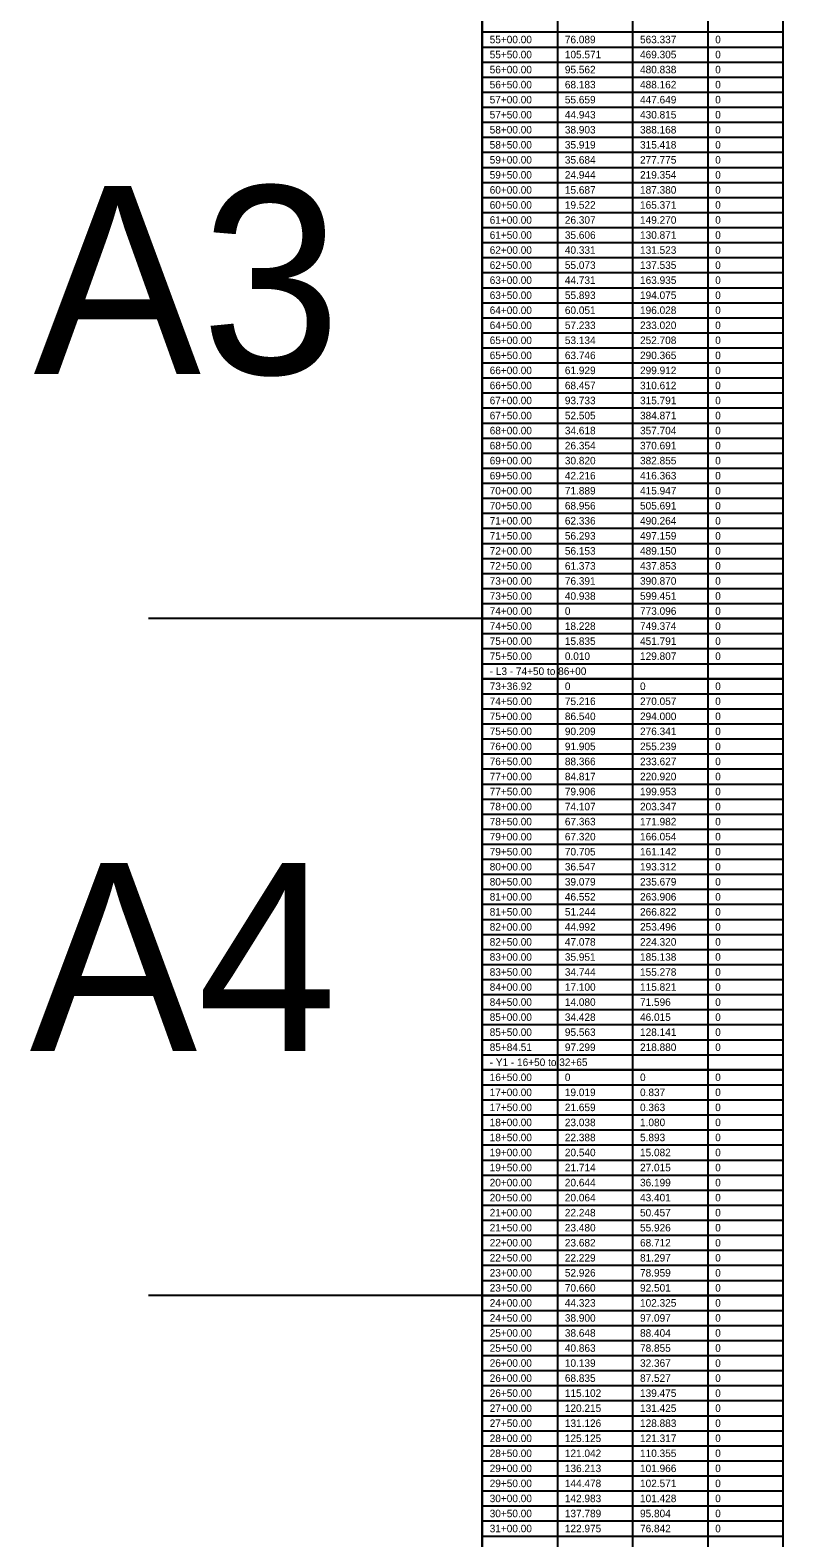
# Model space of a CAD drawing. Extents: x -124 to 80, y -10800 to 19.
# Drawn here: x -120.3 to 80, y -784.5 to -383.5 of the extents above; entities that cross this region are included whole.
import ezdxf

# ---------------------------------------------------------------- set-up
doc = ezdxf.new("R2010")
doc.units = 0
for name, color, linetype in [('Prop Shade Light', 7, 'Continuous'), ('Prop XSC Text', 7, 'Continuous'), ('Scratch_Level_1', 7, 'Continuous'), ('Scratch_Level_3', 7, 'Continuous'), ('Sheet Clip Boundary CELL', 7, 'Continuous')]:
    doc.layers.add(name, color=color, linetype=linetype)

msp = doc.modelspace()

# ---------------------------------------------------------------- linework, layer by layer
at = {"layer": 'Prop Shade Light'}
for points in [[(0, -552), (80, -552), (80, -556), (0, -556)], [(0, -656), (80, -656), (80, -660), (0, -660)]]:
    msp.add_lwpolyline(points, close=True, dxfattribs=at)
at = {"layer": 'Scratch_Level_1'}
for p, q in [((0, 0), (0, -6480)), ((20, 0), (20, -6480)), ((40, 0), (40, -6480)), ((60, 0), (60, -6480)), ((80, 0), (80, -6480)), ((0, -384), (80, -384)), ((0, -388), (80, -388)), ((0, -392), (80, -392)), ((0, -396), (80, -396)), ((0, -400), (80, -400)), ((0, -404), (80, -404)), ((0, -408), (80, -408)), ((0, -412), (80, -412)), ((0, -416), (80, -416)), ((0, -420), (80, -420)), ((0, -424), (80, -424)), ((0, -428), (80, -428)), ((0, -432), (80, -432)), ((0, -436), (80, -436)), ((0, -440), (80, -440)), ((0, -444), (80, -444)), ((0, -448), (80, -448)), ((0, -452), (80, -452)), ((0, -456), (80, -456)), ((0, -460), (80, -460)), ((0, -464), (80, -464)), ((0, -468), (80, -468)), ((0, -472), (80, -472)), ((0, -476), (80, -476)), ((0, -480), (80, -480)), ((0, -484), (80, -484)), ((0, -488), (80, -488)), ((0, -492), (80, -492)), ((0, -496), (80, -496)), ((0, -500), (80, -500)), ((0, -504), (80, -504)), ((0, -508), (80, -508)), ((0, -512), (80, -512)), ((0, -516), (80, -516)), ((0, -520), (80, -520)), ((0, -524), (80, -524)), ((0, -528), (80, -528)), ((0, -532), (80, -532)), ((0, -536), (80, -536)), ((0, -540), (-88.81, -540)), ((0, -540), (80, -540)), ((0, -544), (80, -544)), ((0, -548), (80, -548)), ((0, -552), (80, -552)), ((0, -556), (80, -556)), ((0, -560), (80, -560)), ((0, -564), (80, -564)), ((0, -568), (80, -568)), ((0, -572), (80, -572)), ((0, -576), (80, -576)), ((0, -580), (80, -580)), ((0, -584), (80, -584)), ((0, -588), (80, -588)), ((0, -592), (80, -592)), ((0, -596), (80, -596)), ((0, -600), (80, -600)), ((0, -604), (80, -604)), ((0, -608), (80, -608)), ((0, -612), (80, -612)), ((0, -616), (80, -616)), ((0, -620), (80, -620)), ((0, -624), (80, -624)), ((0, -628), (80, -628)), ((0, -632), (80, -632)), ((0, -636), (80, -636)), ((0, -640), (80, -640)), ((0, -644), (80, -644)), ((0, -648), (80, -648)), ((0, -652), (80, -652)), ((0, -656), (80, -656)), ((0, -660), (80, -660)), ((0, -664), (80, -664)), ((0, -668), (80, -668)), ((0, -672), (80, -672)), ((0, -676), (80, -676)), ((0, -680), (80, -680)), ((0, -684), (80, -684)), ((0, -688), (80, -688)), ((0, -692), (80, -692)), ((0, -696), (80, -696)), ((0, -700), (80, -700)), ((0, -704), (80, -704)), ((0, -708), (80, -708)), ((0, -712), (80, -712)), ((0, -716), (80, -716)), ((0, -720), (-88.81, -720)), ((0, -720), (80, -720)), ((0, -724), (80, -724)), ((0, -728), (80, -728)), ((0, -732), (80, -732)), ((0, -736), (80, -736)), ((0, -740), (80, -740)), ((0, -744), (80, -744)), ((0, -748), (80, -748)), ((0, -752), (80, -752)), ((0, -756), (80, -756)), ((0, -760), (80, -760)), ((0, -764), (80, -764)), ((0, -768), (80, -768)), ((0, -772), (80, -772)), ((0, -776), (80, -776)), ((0, -780), (80, -780)), ((0, -784), (80, -784))]:
    msp.add_line(p, q, dxfattribs=at)
at = {"layer": 'Sheet Clip Boundary CELL'}
for points in [[(0, -360), (80, -360), (80, -540), (0, -540)], [(0, -540), (80, -540), (80, -720), (0, -720)], [(0, -720), (80, -720), (80, -900), (0, -900)]]:
    msp.add_lwpolyline(points, close=True, dxfattribs=at)

# ---------------------------------------------------------------- texts
at = {"layer": 'Prop XSC Text'}
for s, p in [('55+00.00', (2, -387)), ('76.089', (22, -387)), ('563.337', (42, -387)), ('0', (62, -387)), ('55+50.00', (2, -391)), ('105.571', (22, -391)), ('469.305', (42, -391)), ('0', (62, -391)), ('56+00.00', (2, -395)), ('95.562', (22, -395)), ('480.838', (42, -395)), ('0', (62, -395)), ('56+50.00', (2, -399)), ('57+00.00', (2, -403)), ('55.659', (22, -403)), ('68.183', (22, -399)), ('488.162', (42, -399)), ('447.649', (42, -403)), ('0', (62, -399)), ('0', (62, -403)), ('57+50.00', (2, -407)), ('44.943', (22, -407)), ('430.815', (42, -407)), ('0', (62, -407)), ('58+00.00', (2, -411)), ('38.903', (22, -411)), ('388.168', (42, -411)), ('0', (62, -411)), ('58+50.00', (2, -415)), ('35.919', (22, -415)), ('315.418', (42, -415)), ('0', (62, -415)), ('59+00.00', (2, -419)), ('35.684', (22, -419)), ('277.775', (42, -419)), ('0', (62, -419)), ('59+50.00', (2, -423)), ('24.944', (22, -423)), ('219.354', (42, -423)), ('0', (62, -423)), ('60+00.00', (2, -427)), ('15.687', (22, -427)), ('187.380', (42, -427)), ('0', (62, -427)), ('60+50.00', (2, -431)), ('19.522', (22, -431)), ('165.371', (42, -431)), ('0', (62, -431)), ('61+00.00', (2, -435)), ('26.307', (22, -435)), ('149.270', (42, -435)), ('0', (62, -435)), ('61+50.00', (2, -439)), ('35.606', (22, -439)), ('130.871', (42, -439)), ('0', (62, -439)), ('62+00.00', (2, -443)), ('40.331', (22, -443)), ('131.523', (42, -443)), ('0', (62, -443)), ('62+50.00', (2, -447)), ('55.073', (22, -447)), ('137.535', (42, -447)), ('0', (62, -447)), ('63+00.00', (2, -451)), ('44.731', (22, -451)), ('163.935', (42, -451)), ('0', (62, -451)), ('63+50.00', (2, -455)), ('55.893', (22, -455)), ('194.075', (42, -455)), ('0', (62, -455)), ('64+00.00', (2, -459)), ('60.051', (22, -459)), ('196.028', (42, -459)), ('0', (62, -459)), ('64+50.00', (2, -463)), ('57.233', (22, -463)), ('233.020', (42, -463)), ('0', (62, -463)), ('65+00.00', (2, -467)), ('53.134', (22, -467)), ('252.708', (42, -467)), ('0', (62, -467)), ('65+50.00', (2, -471)), ('63.746', (22, -471)), ('290.365', (42, -471)), ('0', (62, -471)), ('66+00.00', (2, -475)), ('61.929', (22, -475)), ('299.912', (42, -475)), ('0', (62, -475)), ('66+50.00', (2, -479)), ('68.457', (22, -479)), ('310.612', (42, -479)), ('0', (62, -479)), ('67+00.00', (2, -483)), ('93.733', (22, -483)), ('315.791', (42, -483)), ('0', (62, -483)), ('67+50.00', (2, -487)), ('52.505', (22, -487)), ('384.871', (42, -487)), ('0', (62, -487)), ('68+00.00', (2, -491)), ('34.618', (22, -491)), ('357.704', (42, -491)), ('0', (62, -491)), ('68+50.00', (2, -495)), ('26.354', (22, -495)), ('370.691', (42, -495)), ('0', (62, -495)), ('69+00.00', (2, -499)), ('30.820', (22, -499)), ('382.855', (42, -499)), ('0', (62, -499)), ('69+50.00', (2, -503)), ('42.216', (22, -503)), ('416.363', (42, -503)), ('0', (62, -503)), ('70+00.00', (2, -507)), ('71.889', (22, -507)), ('415.947', (42, -507)), ('0', (62, -507)), ('70+50.00', (2, -511)), ('68.956', (22, -511)), ('505.691', (42, -511)), ('0', (62, -511)), ('71+00.00', (2, -515)), ('62.336', (22, -515)), ('490.264', (42, -515)), ('0', (62, -515)), ('71+50.00', (2, -519)), ('56.293', (22, -519)), ('497.159', (42, -519)), ('0', (62, -519)), ('72+00.00', (2, -523)), ('56.153', (22, -523)), ('489.150', (42, -523)), ('0', (62, -523)), ('72+50.00', (2, -527)), ('61.373', (22, -527)), ('437.853', (42, -527)), ('0', (62, -527)), ('73+00.00', (2, -531)), ('76.391', (22, -531)), ('390.870', (42, -531)), ('0', (62, -531)), ('73+50.00', (2, -535)), ('40.938', (22, -535)), ('599.451', (42, -535)), ('0', (62, -535)), ('74+00.00', (2, -539)), ('0', (22, -539)), ('773.096', (42, -539)), ('0', (62, -539)), ('74+50.00', (2, -543)), ('18.228', (22, -543)), ('749.374', (42, -543)), ('0', (62, -543)), ('75+00.00', (2, -547)), ('15.835', (22, -547)), ('451.791', (42, -547)), ('0', (62, -547)), ('75+50.00', (2, -551)), ('0.010', (22, -551)), ('129.807', (42, -551)), ('0', (62, -551)), ('- L3 - 74+50 to 86+00', (2, -555)), ('73+36.92', (2, -559)), ('0', (22, -559)), ('0', (42, -559)), ('0', (62, -559)), ('74+50.00', (2, -563)), ('75.216', (22, -563)), ('270.057', (42, -563)), ('0', (62, -563)), ('75+00.00', (2, -567)), ('86.540', (22, -567)), ('294.000', (42, -567)), ('0', (62, -567)), ('75+50.00', (2, -571)), ('90.209', (22, -571)), ('276.341', (42, -571)), ('0', (62, -571)), ('76+00.00', (2, -575)), ('91.905', (22, -575)), ('255.239', (42, -575)), ('0', (62, -575)), ('76+50.00', (2, -579)), ('88.366', (22, -579)), ('233.627', (42, -579)), ('0', (62, -579)), ('77+00.00', (2, -583)), ('84.817', (22, -583)), ('220.920', (42, -583)), ('0', (62, -583)), ('77+50.00', (2, -587)), ('79.906', (22, -587)), ('199.953', (42, -587)), ('0', (62, -587)), ('78+00.00', (2, -591)), ('74.107', (22, -591)), ('203.347', (42, -591)), ('0', (62, -591)), ('78+50.00', (2, -595)), ('67.363', (22, -595)), ('171.982', (42, -595)), ('0', (62, -595)), ('79+00.00', (2, -599)), ('67.320', (22, -599)), ('166.054', (42, -599)), ('0', (62, -599)), ('79+50.00', (2, -603)), ('70.705', (22, -603)), ('161.142', (42, -603)), ('0', (62, -603)), ('80+00.00', (2, -607)), ('36.547', (22, -607)), ('193.312', (42, -607)), ('0', (62, -607)), ('80+50.00', (2, -611)), ('39.079', (22, -611)), ('235.679', (42, -611)), ('0', (62, -611)), ('81+00.00', (2, -615)), ('46.552', (22, -615)), ('263.906', (42, -615)), ('0', (62, -615)), ('81+50.00', (2, -619)), ('51.244', (22, -619)), ('266.822', (42, -619)), ('0', (62, -619)), ('82+00.00', (2, -623)), ('44.992', (22, -623)), ('253.496', (42, -623)), ('0', (62, -623)), ('82+50.00', (2, -627)), ('47.078', (22, -627)), ('224.320', (42, -627)), ('0', (62, -627)), ('83+00.00', (2, -631)), ('35.951', (22, -631)), ('185.138', (42, -631)), ('0', (62, -631)), ('83+50.00', (2, -635)), ('34.744', (22, -635)), ('155.278', (42, -635)), ('0', (62, -635)), ('84+00.00', (2, -639)), ('17.100', (22, -639)), ('115.821', (42, -639)), ('0', (62, -639)), ('84+50.00', (2, -643)), ('14.080', (22, -643)), ('71.596', (42, -643)), ('0', (62, -643)), ('85+00.00', (2, -647)), ('34.428', (22, -647)), ('46.015', (42, -647)), ('0', (62, -647)), ('85+50.00', (2, -651)), ('95.563', (22, -651)), ('128.141', (42, -651)), ('0', (62, -651)), ('85+84.51', (2, -655)), ('97.299', (22, -655)), ('218.880', (42, -655)), ('0', (62, -655)), ('- Y1 - 16+50 to 32+65', (2, -659)), ('16+50.00', (2, -663)), ('0', (22, -663)), ('0', (42, -663)), ('0', (62, -663)), ('17+00.00', (2, -667)), ('19.019', (22, -667)), ('0.837', (42, -667)), ('0', (62, -667)), ('17+50.00', (2, -671)), ('21.659', (22, -671)), ('0.363', (42, -671)), ('0', (62, -671)), ('18+00.00', (2, -675)), ('23.038', (22, -675)), ('1.080', (42, -675)), ('0', (62, -675)), ('18+50.00', (2, -679)), ('22.388', (22, -679)), ('5.893', (42, -679)), ('0', (62, -679)), ('19+00.00', (2, -683)), ('20.540', (22, -683)), ('15.082', (42, -683)), ('0', (62, -683)), ('19+50.00', (2, -687)), ('21.714', (22, -687)), ('27.015', (42, -687)), ('0', (62, -687)), ('20+00.00', (2, -691)), ('20.644', (22, -691)), ('36.199', (42, -691)), ('0', (62, -691)), ('20+50.00', (2, -695)), ('20.064', (22, -695)), ('43.401', (42, -695)), ('0', (62, -695)), ('21+00.00', (2, -699)), ('22.248', (22, -699)), ('50.457', (42, -699)), ('0', (62, -699)), ('21+50.00', (2, -703)), ('23.480', (22, -703)), ('55.926', (42, -703)), ('0', (62, -703)), ('22+00.00', (2, -707)), ('23.682', (22, -707)), ('68.712', (42, -707)), ('0', (62, -707)), ('22+50.00', (2, -711)), ('22.229', (22, -711)), ('81.297', (42, -711)), ('0', (62, -711)), ('23+00.00', (2, -715)), ('52.926', (22, -715)), ('78.959', (42, -715)), ('0', (62, -715)), ('23+50.00', (2, -719)), ('70.660', (22, -719)), ('92.501', (42, -719)), ('0', (62, -719)), ('24+00.00', (2, -723)), ('44.323', (22, -723)), ('102.325', (42, -723)), ('0', (62, -723)), ('24+50.00', (2, -727)), ('38.900', (22, -727)), ('97.097', (42, -727)), ('0', (62, -727)), ('25+00.00', (2, -731)), ('38.648', (22, -731)), ('88.404', (42, -731)), ('0', (62, -731)), ('25+50.00', (2, -735)), ('40.863', (22, -735)), ('78.855', (42, -735)), ('0', (62, -735)), ('26+00.00', (2, -739)), ('10.139', (22, -739)), ('32.367', (42, -739)), ('0', (62, -739)), ('26+00.00', (2, -743)), ('68.835', (22, -743)), ('87.527', (42, -743)), ('0', (62, -743)), ('26+50.00', (2, -747)), ('115.102', (22, -747)), ('139.475', (42, -747)), ('0', (62, -747)), ('27+00.00', (2, -751)), ('120.215', (22, -751)), ('131.425', (42, -751)), ('0', (62, -751)), ('27+50.00', (2, -755)), ('131.126', (22, -755)), ('128.883', (42, -755)), ('0', (62, -755)), ('28+00.00', (2, -759)), ('125.125', (22, -759)), ('121.317', (42, -759)), ('0', (62, -759)), ('28+50.00', (2, -763)), ('121.042', (22, -763)), ('110.355', (42, -763)), ('0', (62, -763)), ('29+00.00', (2, -767)), ('136.213', (22, -767)), ('101.966', (42, -767)), ('0', (62, -767)), ('29+50.00', (2, -771)), ('144.478', (22, -771)), ('102.571', (42, -771)), ('0', (62, -771)), ('30+00.00', (2, -775)), ('142.983', (22, -775)), ('101.428', (42, -775)), ('0', (62, -775)), ('30+50.00', (2, -779)), ('137.789', (22, -779)), ('95.804', (42, -779)), ('0', (62, -779)), ('31+00.00', (2, -783)), ('122.975', (22, -783)), ('76.842', (42, -783)), ('0', (62, -783))]:
    msp.add_text(s, height=2, dxfattribs=at).set_placement(p)
at = {"layer": 'Scratch_Level_3'}
for s, p in [('A3', (-119.39, -475)), ('A4', (-120.4, -655))]:
    msp.add_text(s, height=50, dxfattribs=at).set_placement(p)

doc.saveas('drawing.dxf')
